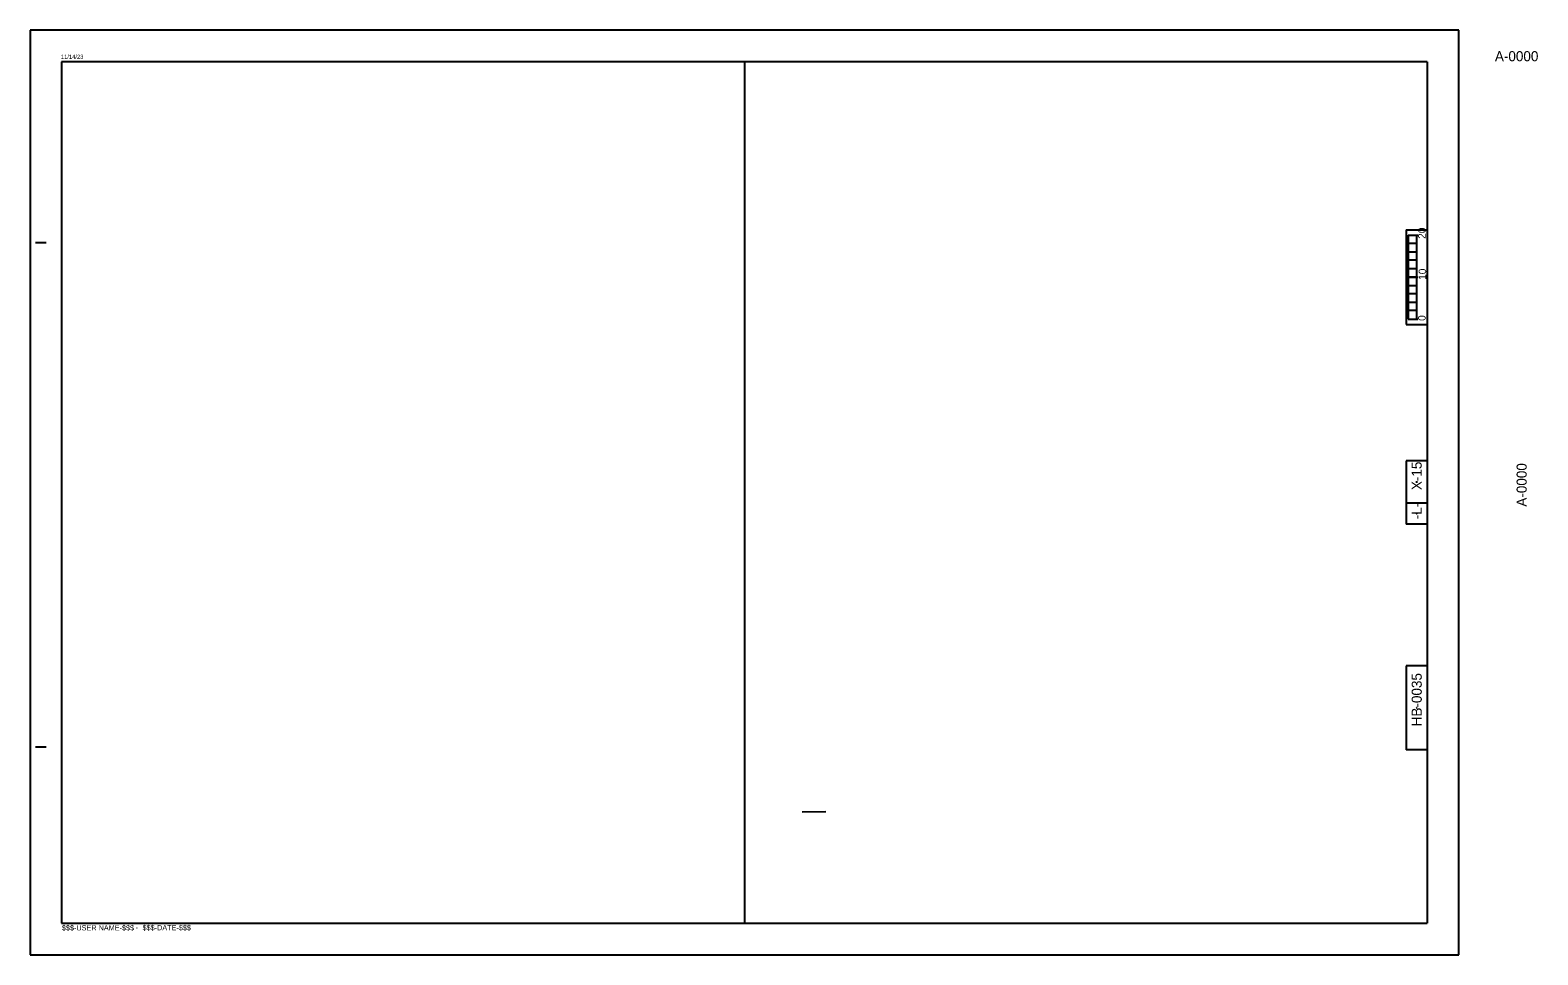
# Model space of a CAD drawing. Extents: x -2.69 to 2.99, y 0 to 1.83.
# Drawn here: x 0 to 2.99, y 0 to 1.833 of the extents above; entities that cross this region are included whole.
import ezdxf

# ---------------------------------------------------------------- set-up
doc = ezdxf.new("R2010")
doc.units = 0
for name, color, linetype in [('E_RDY_TC_Pavement', 7, 'Continuous'), ('P_NCDOT_XS_Sheet_Alignment_Station_Label', 7, 'Continuous'), ('P_NCDOT_XS_Sheet_Grid_Border', 7, 'Continuous'), ('Sheet_Grid_Major', 7, 'Continuous'), ('Sheet_Grid_Middle', 7, 'Continuous'), ('Sheet_Grid_Minor', 7, 'Continuous')]:
    doc.layers.add(name, color=color, linetype=linetype)

msp = doc.modelspace()

# ---------------------------------------------------------------- linework, layer by layer
at = {"layer": 'E_RDY_TC_Pavement'}
msp.add_line((1.531, 0.2835), (1.5778, 0.2841), dxfattribs=at)
at = {"layer": 'P_NCDOT_XS_Sheet_Alignment_Station_Label'}
for p, q in [((2.7332, 1.4272), (2.7521, 1.4272)), ((2.7332, 1.4272), (2.7332, 1.2605)), ((2.7416, 1.4272), (2.7503, 1.4272)), ((2.7499, 1.4272), (2.7499, 1.2605)), ((2.7332, 1.3438), (2.7521, 1.3438)), ((2.7332, 1.2605), (2.7521, 1.2605)), ((2.7416, 1.2605), (2.7503, 1.2605))]:
    msp.add_line(p, q, dxfattribs=at)
for points in [[(2.7332, 1.4272), (2.7499, 1.4272), (2.7499, 1.4105), (2.7332, 1.4105)], [(2.7332, 1.3938), (2.7499, 1.3938), (2.7499, 1.3772), (2.7332, 1.3772)], [(2.7332, 1.3605), (2.7499, 1.3605), (2.7499, 1.3438), (2.7332, 1.3438)], [(2.7332, 1.3272), (2.7499, 1.3272), (2.7499, 1.3105), (2.7332, 1.3105)], [(2.7332, 1.2938), (2.7499, 1.2938), (2.7499, 1.2772), (2.7332, 1.2772)]]:
    msp.add_lwpolyline(points, close=True, dxfattribs=at)
at = {"layer": 'Sheet_Grid_Major'}
for p, q in [((2.8333, 1.8333), (0, 1.8333)), ((0, 1.8333), (0, 0)), ((2.8333, 0), (2.8333, 1.8333)), ((1.4167, 1.7708), (1.4166, 0.0625)), ((0, 0), (2.8333, 0))]:
    msp.add_line(p, q, dxfattribs=at)
for centre in [(2.7499, 1.3437), (2.7499, 0.9375), (2.7499, 0.875), (2.75, 0.4897)]:
    msp.add_circle(centre, 0.0001, dxfattribs=at)
at = {"layer": 'Sheet_Grid_Minor'}
for p, q in [((0.0625, 1.7708), (0.0625, 0.0625)), ((2.7708, 1.7708), (0.0625, 1.7708)), ((0.1027, 1.7844), (0.1027, 1.7844)), ((2.7708, 1.7708), (2.7708, 0.0625)), ((2.7292, 1.4375), (2.7292, 1.25)), ((2.7292, 1.4375), (2.7708, 1.4375)), ((0.0108, 1.4125), (0.0317, 1.4126)), ((2.7292, 1.25), (2.7708, 1.25)), ((2.7292, 0.9792), (2.7292, 0.8542)), ((2.7708, 0.9792), (2.7292, 0.9792)), ((2.7708, 0.8958), (2.7292, 0.8958)), ((2.7708, 0.8542), (2.7292, 0.8542)), ((2.7292, 0.5729), (2.7292, 0.4062)), ((2.7708, 0.5729), (2.7292, 0.5729)), ((0.0109, 0.4125), (0.0317, 0.4125)), ((2.7708, 0.4062), (2.7292, 0.4062)), ((0.0625, 0.0625), (2.7708, 0.0625))]:
    msp.add_line(p, q, dxfattribs=at)

# ---------------------------------------------------------------- texts
at = {"layer": 'P_NCDOT_XS_Sheet_Alignment_Station_Label'}
for s, p in [('20', (2.7678, 1.4196)), ('10', (2.7688, 1.3382)), ('0', (2.7677, 1.2569))]:
    msp.add_text(s, height=0.015, rotation=90, dxfattribs=at).set_placement(p)
at = {"layer": 'P_NCDOT_XS_Sheet_Grid_Border'}
for s, p in [('X-15', (2.7599, 0.9214)), ('-L-', (2.7599, 0.8636))]:
    msp.add_text(s, height=0.02, rotation=90, dxfattribs=at).set_placement(p)
at = {"layer": 'Sheet_Grid_Middle'}
msp.add_text('A-0000', height=0.02, dxfattribs=at).set_placement((2.9051, 1.7717))
for s, p in [('A-0000', (2.9681, 0.8886)), ('HB-0035', (2.76, 0.4531))]:
    msp.add_text(s, height=0.02, rotation=90, dxfattribs=at).set_placement(p)
at = {"layer": 'Sheet_Grid_Minor'}
msp.add_text('11/14/23', height=0.00833, rotation=0, dxfattribs=at).set_placement((0.0609, 1.7764))
for s, height, p in [('$$$-DATE-$$$', 0.010417, (0.223, 0.0486)), ('$$$-USER NAME-$$$', 0.010417, (0.063, 0.0484)), ('-', 0.0104, (0.2093, 0.0494))]:
    msp.add_text(s, height=height, dxfattribs=at).set_placement(p)

doc.saveas('drawing.dxf')
